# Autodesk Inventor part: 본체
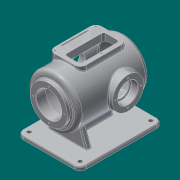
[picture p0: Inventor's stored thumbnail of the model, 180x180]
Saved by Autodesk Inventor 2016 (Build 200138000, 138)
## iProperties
Created: 2016-02
Part Number: 본체
Material: 알루미늄 6061
Document SubType Name: Modeling
Designer: mduedu
Density: 2.71 g/cm^3
Appearance: 알루미늄 - 평지
Author: mduedu
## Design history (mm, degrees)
sketch "스케치2"
  geometry: L1 (0, 100)-(0, -100); L2 (65, -75.993)-(65, 100); L3 (65, 100)-(0, 100); A1 r 100 centre (0, 0) between (0, -100) and (65, -75.993); 2 further points
  constraints: 6 end point, 2 midpoint, 2 point on circle, 1 centre point, 1 coincident, 1 horizontal, 1 parallel, 1 vertical
  dimensions: "d3" = 200 distance of L1.start L1.end; "d5" = 130 diameter of L2 L1; "d6" = 100 radius of A1
revolve "회전1" sketch "스케치2" stored, may be unused: angle "d7" = 90 deg
sketch "스케치3"
  geometry: C1 r 47.5 at (0, 0); 1 further point
  constraints: 1 centre point, 1 coincident
  dimensions: "d8" = 95 diameter of C1
extrude "돌출2" join sketch "스케치3" distance "d10" = 10; taper "d11" = 0 deg
sketch "스케치5"
  geometry: L1 (47.5, 110)-(47.5, 100) reference; L2 (47.5, 100)-(65, 100) reference; L3 (65, 100)-(65, -75.993) reference; L4 (-65, -75.993)-(-65, 100) reference; L5 (-65, 100)-(-47.5, 100) reference; L6 (-47.5, 100)-(-47.5, 110) reference; L7 (-47.5, 110)-(47.5, 110) reference; L8 (55, 85)-(55, -71.239); L9 (0, 85)-(55, 85); L10 (0, 85)-(0, -90); A1 r 100 centre (0, 0) between (0, -100) and (65, -75.993) reference; A2 r 100 centre (0, 0) between (-65, -75.993) and (0, -100) reference; A3 r 90 centre (0, 0) between (0, -90) and (55, -71.239); 1 further point
  constraints: 6 end point, 2 point on circle, 1 centre point, 1 parallel, 1 perpendicular, 1 point on line, 1 vertical
  dimensions: "d13" = 10 distance between parallel lines of L3 L8; "d14" = 10 radial gap between concentric circles of A3 A1; "d15" = 15 distance between parallel lines of L9 L2
revolve "회전2" sketch "스케치5" stored, may be unused: angle "d16" = 90 deg
hole "구멍1" diameter "d19" = 65; stored, may be unused: countersink angle "d23" = 90 deg, drill point angle "d25" = 118 deg; dims "d17" = 10, "d18" = 10, "d20" = 6, "d21" = 4, "d22" = 2, "d24" = 8
node "작업 평면1"
sketch "스케치6"
  geometry: L1 (47.5, 110)-(-47.5, 110) reference; C1 r 40 at (0, -17); 1 further point
  constraints: 1 centre point, 1 vertical alignment
  dimensions: "d27" = 80 diameter of C1; "d29" = 127 distance from line of C1.centre L1
extrude "돌출3" join sketch "스케치6" stored distance "d30" = 10; taper "d31" = 0 deg
hole "구멍2" diameter "d34" = 42; stored, may be unused: countersink angle "d38" = 90 deg, drill point angle "d40" = 118 deg; dims "d32" = 10, "d33" = 10, "d35" = 6, "d36" = 52, "d37" = 18, "d39" = 8
sketch "스케치7" dims "d41" = 65
  geometry: C1 r 40 at (0, 0) reference; 3 further points
  constraints: 2 vertical alignment, 1 coincident, 2 other
hole "구멍3" sketch "스케치7" at (0, 32.5) diameter "d43" = 3.242; stored, may be unused: countersink angle "d47" = 90 deg, drill point angle "d49" = 118 deg; dims "d44" = 11, "d45" = 13, "d46" = 18, "d48" = 13
sketch "스케치8" dims "d53" = 80
  geometry: 3 further points
  constraints: 2 vertical alignment, 1 coincident, 2 other
hole "구멍4" sketch "스케치8" at (0, 40) diameter "d56" = 3.242; stored, may be unused: countersink angle "d60" = 90 deg, drill point angle "d62" = 118 deg; dims "d57" = 11, "d58" = 13, "d59" = 18, "d61" = 13
fillet "모깎기1" dims "d66" = 10
fillet "모깎기2" dims "d67" = 3
fillet "모깎기3" dims "d68" = 0.3
chamfer "모따기1" distance "d69" = 1; stored, may be unused: second distance "d70" = 2, angle "d71" = 45 deg
node "작업 평면5"
sketch "스케치10"
  geometry: L1 (-50, 0)-(50, 0); L2 (-50, 64)-(50, 64); L3 (50, 64)-(50, 50); L4 (50, 50)-(-50, 50); L5 (-50, 50)-(-50, 64); 3 further points
  constraints: 10 end point, 2 horizontal, 2 midpoint, 2 vertical, 1 coincident, 1 vertical alignment
  dimensions: "d132" = 100 distance of L1.start L1.end; "d158" = 50 distance between parallel lines of L4 L1; "d159" = 14 distance of L2.end L3.end; "d160" = 100 distance of L2.start L2.end
extrude "돌출5" join sketch "스케치10" stored distance "d84" = 10; taper "d85" = 0 deg
feature "면 기울기3" dims angle "d135" = 20 deg
sketch "스케치11"
  geometry: L1 (-100, 64)-(-100, 50) reference; L2 (-100, 50)-(-100, -50); L3 (-65, 90)-(-65, -71.239) reference; L4 (-100, -50)-(-65, -50); L5 (-100, 50)-(-55.515, 50) reference; 1 further point
  constraints: 4 end point, 1 collinear, 1 perpendicular, 1 point on line
  dimensions: "d161" = 100 distance between parallel lines of L4 L5
feature "리브1" sketch "스케치11" dims "d88" = 1, "d89" = 8, "d90" = 0, "d91" = 0, "d92" = 1, "d93" = 1
fillet "모깎기5" dims "d103" = 3
fillet "모깎기6" dims "d105" = 3
node "작업 평면6"
sketch "스케치15"
  geometry: L1 (-30, 60)-(50, 60); L2 (50, 60)-(50, -60); L3 (50, -60)-(-30, -60); L4 (-30, -60)-(-30, 60); 3 further points
  constraints: 8 end point, 2 parallel, 1 horizontal, 1 horizontal alignment, 1 midpoint, 1 perpendicular, 1 vertical alignment
  dimensions: "d110" = 80 distance of L2.end L3.end; "d112" = 60 distance from line of L3 point (10, 0); "d113" = 120 distance of L1.end L2.end; "d149" = 30 distance from line of L4 point (0, 0)
extrude "돌출8" join sketch "스케치15" stored distance "d114" = 10; taper "d115" = 0 deg
fillet "모깎기7" dims "d116" = 15
sketch "스케치16"
  geometry: L1 (-30, -45)-(-30, 45) reference; L2 (-15, 60)-(35, 60) reference; L3 (35, -60)-(-15, -60) reference; L4 (-20, -45)-(-20, 45); L5 (-15, 50)-(15, 50); L6 (20, 45)-(20, -45); L7 (15, -50)-(-15, -50); L8 (50, 45)-(50, -45) reference; A1 r 15 centre (-15, -45) between (-30, -45) and (-15, -60) reference; A2 r 15 centre (-15, 45) between (-15, 60) and (-30, 45) reference; A3 r 5 centre (-15, -45) between (-20, -45) and (-15, -50); A4 r 5 centre (-15, 45) between (-15, 50) and (-20, 45); A5 r 5 centre (15, 45) between (20, 45) and (15, 50); A6 r 5 centre (15, -45) between (15, -50) and (20, -45); A7 r 15 centre (35, 45) between (50, 45) and (35, 60) reference; A8 r 15 centre (35, -45) between (35, -60) and (50, -45) reference
  constraints: 8 end point, 8 point on circle, 4 centre point, 2 equal radius, 3 other
  dimensions: "d137" = 10 distance between parallel lines of L4 L1; "d150" = 40 distance between parallel lines of L6 L4; "d151" = 100 distance between parallel lines of L7 L5
extrude "돌출9" cut sketch "스케치16" stored distance "d118" = 10; taper "d119" = 0 deg
fillet "모깎기8" dims "d120" = 3
sketch "스케치17"
  geometry: L1 (-30, -45)-(-30, 45) reference; L2 (-20, 45)-(-20, -45) reference; L3 (-15, -50)-(15, -50) reference; L4 (20, -45)-(20, 45) reference; L5 (15, 50)-(-15, 50) reference; L6 (-15, 60)-(35, 60) reference; L7 (35, -60)-(-15, -60) reference; L8 (15, 55)-(-15, 55); L9 (-25, 45)-(-25, -45); L10 (-15, -55)-(15, -55); L11 (25, -45)-(25, 45); L12 (50, 45)-(50, -45) reference; L13 (35, 55)-(-15, 55); L14 (-25, 45)-(-25, -45); L15 (-15, -55)-(35, -55); L16 (45, -45)-(45, 45); A1 r 5 centre (-15, 45) between (-15, 50) and (-20, 45) reference; A2 r 5 centre (-15, -45) between (-20, -45) and (-15, -50) reference; A3 r 5 centre (15, -45) between (15, -50) and (20, -45) reference; A4 r 5 centre (15, 45) between (20, 45) and (15, 50) reference; A5 r 15 centre (-15, 45) between (-15, 60) and (-30, 45) reference; A6 r 15 centre (-15, -45) between (-30, -45) and (-15, -60) reference; A7 r 10 centre (-15, 45) between (-15, 55) and (-25, 45); A8 r 10 centre (-15, -45) between (-25, -45) and (-15, -55); A9 r 10 centre (15, -45) between (15, -55) and (25, -45); A10 r 10 centre (15, 45) between (25, 45) and (15, 55); A11 r 15 centre (35, 45) between (50, 45) and (35, 60) reference; A12 r 15 centre (35, -45) between (35, -60) and (50, -45) reference; A13 r 10 centre (-15, 45) between (-15, 55) and (-25, 45); A14 r 10 centre (-15, -45) between (-25, -45) and (-15, -55); A15 r 10 centre (35, -45) between (35, -55) and (45, -45); A16 r 10 centre (35, 45) between (45, 45) and (35, 55); 6 further points
  constraints: 18 point on circle, 16 end point, 8 centre point, 4 midpoint, 4 tangent, 11 other
  dimensions: "d138" = 5 distance between parallel lines of L8 L6; "d157" = 5 distance between parallel lines of L12 L16
hole "구멍5" sketch "스케치17" at (-25, 0), (42.071, 52.071), (42.071, -52.071) diameter "d122" = 3.242; stored, may be unused: countersink angle "d126" = 90 deg, drill point angle "d128" = 118 deg; dims "d123" = 9, "d124" = 13, "d125" = 18, "d127" = 11
sketch "스케치19"
  geometry: L1 (-50, 70)-(-35, 70) reference; L2 (-50, 42.603)-(-50, 70) reference; C1 r 2.5 at (-43, 70); 1 further point
  constraints: 1 centre point, 1 point on line
  dimensions: "d152" = 5 diameter of C1; "d153" = 7 distance from line of C1.centre L2
extrude "돌출11" cut sketch "스케치19" stored distance "d154" = 70; taper "d155" = 0 deg
fillet "모깎기11" dims "d156" = 2.5
sketch "스케치20"
  geometry: L1 (-80, 110)-(80, 110); L2 (80, 110)-(80, -100); L3 (80, -100)-(-80, -100); L4 (-80, -100)-(-80, 110); 2 further points
  constraints: 8 end point, 2 parallel, 1 horizontal, 1 midpoint, 1 perpendicular, 1 vertical alignment
  dimensions: "d162" = 160 distance of L1.start L1.end; "d164" = 210 distance of L1.end L2.end; "d165" = 110 distance from line of L1 point (0, 0)
extrude "돌출12" join sketch "스케치20" distance "d166" = 10; taper "d167" = 0 deg
fillet "모깎기12" dims "d168" = 15
fillet "모깎기13" dims "d169" = 3
fillet "모깎기14" dims "d170" = 3
sketch "스케치21"
  geometry: C1 r 5 at (-65, -95); C2 r 5 at (65, -95); C3 r 5 at (65, 85); C4 r 5 at (-65, 85); A1 r 15 centre (-65, -95) between (-80, -95) and (-65, -110) reference; A2 r 15 centre (-65, 85) between (-65, 100) and (-80, 85) reference; A3 r 15 centre (65, 85) between (80, 85) and (65, 100) reference; A4 r 15 centre (65, -95) between (65, -110) and (80, -95) reference; 1 further point
  constraints: 4 centre point, 4 coincident, 3 equal radius
  dimensions: "d171" = 10 diameter of C1
extrude "돌출13" cut sketch "스케치21" stored distance "d172" = 10; taper "d173" = 0 deg
sketch "스케치22"
  geometry: L1 (80, -95)-(80, 85) reference; 2 further points
  constraints: 1 horizontal alignment, 1 other
  dimensions: "d174" = 15 distance from line of L1 point (65, 0)
feature "엠보싱2" sketch "스케치22" dims "d13" = 10, "d175" = 0.5, "d176" = 0
node "솔리드2"
pattern_circular "원형 패턴1" dims angle "d51" = 360 deg
mirror "대칭1"
pattern_circular "원형 패턴2" dims angle "d64" = 360 deg
node "절단 모서리 투영1"
node "절단 모서리 투영2"
node "절단 모서리 투영3"
other parameters: "d26" = 75
